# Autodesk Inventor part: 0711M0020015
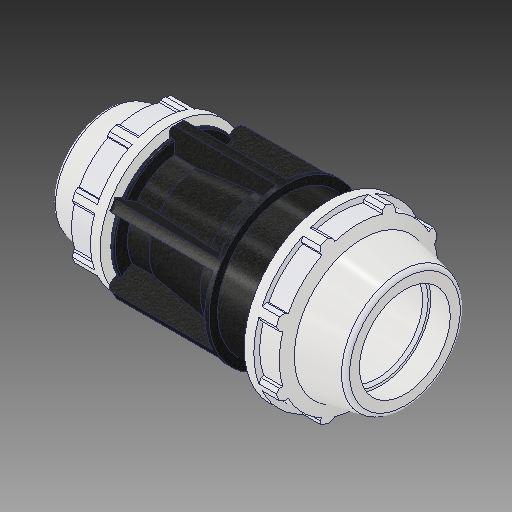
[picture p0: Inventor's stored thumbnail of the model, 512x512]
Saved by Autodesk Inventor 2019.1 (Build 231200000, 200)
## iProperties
Created: 2017-02
Part Number: 0711M0020015
Material: PVC-Piping
Description: PLASSON REDUCING COUPLER 2'' - 1 1/2''
Document SubType Name: Modeling
Designer: KIM
Mass: 92.6774 g
Surface Area: 199.44 cm^2
Volume: 66.1981 cm^3
Density: 1.4 g/cm^3
Appearance: PTFE
Author: KIM
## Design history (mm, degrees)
derived "0711M0.ipt"
feature "Solid1::0711M0.ipt"
tag "TaggingFeature1"
body "Solid1"
other parameters: "d2" = 60.1, "d4" = 16.41667, "d5" = 28.14286, "d7" = 113.03, "d9" = 28.14286, "d11" = 2.81429, "d12" = 90.424, "d13" = 120 deg, "d14" = 78.13, "d15" = 12 deg, "d16" = 101.727, "d18" = 3.005, "d19" = 35 deg, "d20" = 17.5 deg, "d21" = 105.1179, "d23" = 0, "d25" = 360 deg, "d27" = 2.2606, "d42" = 21.67, "d46" = 1.803, "d51" = 197, "d52" = 67.93103, "d53" = 12 deg, "d54" = 96.012, "d56" = 72.15, "d57" = 48.1, "d58" = 54.09, "d59" = 43.29, "d60" = 86.4108, "d61" = 76.8096, "d62" = 19.7, "d63" = 23.64, "d64" = 120 deg, "d65" = 96.012, "d68" = 14.07143, "d74" = 89.29116, "d75" = 35 deg, "d76" = 17.5 deg, "d78" = 0, "d80" = 360 deg, "d85" = 1.92024, "d88" = 0.962, "d93" = 62, "d94" = 79.121, "d97" = 3.37017, "d98" = 6.4008, "d99" = 0, "d100" = 4.5212, "d102" = 360 deg, "d104" = 2, "d106" = 0, "d107" = 6.4008, "d108" = 0, "d109" = 6.4008, "d110" = 0, "d_" = 60.1, "E_" = 113.03, "H_" = 197, "l_" = 96.012, "d_1" = 48.1, "E_1" = 96.012, "l_1" = 62, "d96" = 10.1105
